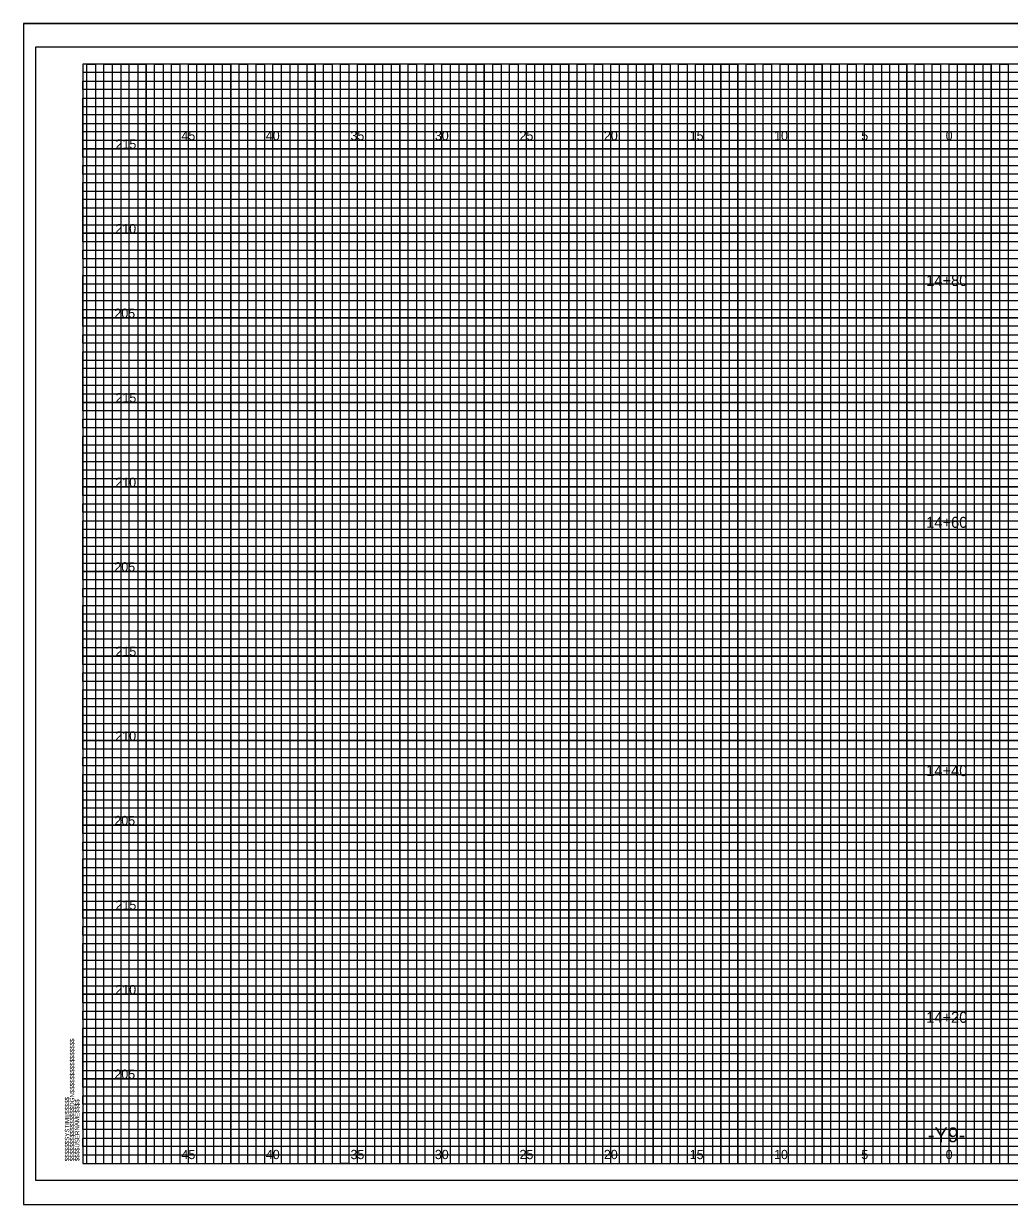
# Model space of a CAD drawing. Extents: x -4 to 103, y -2 to 492.
# Drawn here: x -3.5 to 54.8, y 280.9 to 350.7 of the extents above; entities that cross this region are included whole.
import ezdxf

# ---------------------------------------------------------------- set-up
doc = ezdxf.new("R2010")
doc.units = 0
for name, color, linetype in [('Old_Level_10', 7, 'Continuous'), ('Old_Level_16', 7, 'Continuous'), ('Old_Level_3', 7, 'Continuous'), ('Old_Level_5', 7, 'Continuous'), ('Old_Level_8', 7, 'Continuous'), ('Prop Dimension', 7, 'Continuous'), ('Prop Terminator CELL', 7, 'Continuous'), ('Prop XS Finish Grade', 7, 'Continuous'), ('Prop XS Finish Grade Earthwork', 7, 'Continuous'), ('Prop XS SE Text', 7, 'Continuous'), ('Prop XSC Text', 7, 'Continuous')]:
    doc.layers.add(name, color=color, linetype=linetype)

msp = doc.modelspace()

# ---------------------------------------------------------------- linework, layer by layer
at = {"layer": 'Old_Level_10'}
for p, q in [((1.25, 283.3), (1.25, 348.3)), ((3.75, 283.3), (3.75, 348.3)), ((6.25, 283.3), (6.25, 348.3)), ((8.75, 283.3), (8.75, 348.3)), ((11.25, 283.3), (11.25, 348.3)), ((13.75, 283.3), (13.75, 348.3)), ((16.25, 283.3), (16.25, 348.3)), ((18.75, 283.3), (18.75, 348.3)), ((21.25, 283.3), (21.25, 348.3)), ((23.75, 283.3), (23.75, 348.3)), ((26.25, 283.3), (26.25, 348.3)), ((28.75, 283.3), (28.75, 348.3)), ((31.25, 283.3), (31.25, 348.3)), ((33.75, 283.3), (33.75, 348.3)), ((36.25, 283.3), (36.25, 348.3)), ((38.75, 283.3), (38.75, 348.3)), ((41.25, 283.3), (41.25, 348.3)), ((43.75, 283.3), (43.75, 348.3)), ((46.25, 283.3), (46.25, 348.3)), ((48.75, 283.3), (48.75, 348.3)), ((51.25, 283.3), (51.25, 348.3)), ((53.75, 283.3), (53.75, 348.3)), ((0, 345.8), (74.25, 345.8)), ((0, 343.3), (102.5, 343.3)), ((0, 340.8), (102.5, 340.8)), ((0, 338.3), (102.5, 338.3)), ((0, 335.8), (102.5, 335.8)), ((0, 333.3), (102.5, 333.3)), ((0, 330.8), (102.5, 330.8)), ((0, 328.3), (102.5, 328.3)), ((0, 325.8), (102.5, 325.8)), ((0, 323.3), (102.5, 323.3)), ((0, 320.8), (102.5, 320.8)), ((0, 318.3), (102.5, 318.3)), ((0, 315.8), (102.5, 315.8)), ((0, 313.3), (102.5, 313.3)), ((0, 310.8), (102.5, 310.8)), ((0, 308.3), (102.5, 308.3)), ((0, 305.8), (102.5, 305.8)), ((0, 303.3), (102.5, 303.3)), ((0, 300.8), (102.5, 300.8)), ((0, 298.3), (102.5, 298.3)), ((0, 295.8), (102.5, 295.8)), ((0, 293.3), (102.5, 293.3)), ((0, 290.8), (102.5, 290.8)), ((0, 288.3), (102.5, 288.3)), ((0, 285.8), (102.5, 285.8))]:
    msp.add_line(p, q, dxfattribs=at)
at = {"layer": 'Old_Level_3'}
for p, q in [((-3.5, 350.7), (103.4, 350.7)), ((-3.5, 350.7), (-3.5, 280.875)), ((-3.5, 280.875), (103.4, 280.875))]:
    msp.add_line(p, q, dxfattribs=at)
at = {"layer": 'Old_Level_5'}
msp.add_lwpolyline([(103.4, 350.7), (-3.5, 350.7), (-3.5, 280.875), (103.4, 280.875)], close=True, dxfattribs=at)
at = {"layer": 'Old_Level_8'}
for points in [[(1.25, 283.3), (1.25, 348.3), (3.75, 348.3), (3.75, 283.3), (6.25, 283.3), (6.25, 348.3), (8.75, 348.3), (8.75, 283.3), (11.25, 283.3), (11.25, 348.3), (13.75, 348.3), (13.75, 283.3), (16.25, 283.3), (16.25, 348.3), (18.75, 348.3), (18.75, 283.3), (21.25, 283.3), (21.25, 348.3), (23.75, 348.3), (23.75, 283.3), (26.25, 283.3), (26.25, 348.3), (28.75, 348.3), (28.75, 283.3), (31.25, 283.3), (31.25, 348.3), (33.75, 348.3), (33.75, 283.3), (36.25, 283.3), (36.25, 348.3), (38.75, 348.3), (38.75, 283.3), (41.25, 283.3), (41.25, 348.3), (43.75, 348.3), (43.75, 283.3), (46.25, 283.3), (46.25, 348.3), (48.75, 348.3), (48.75, 283.3), (51.25, 283.3), (51.25, 348.3), (53.75, 348.3), (53.75, 283.3)], [(102.5, 343.3), (0, 343.3), (0, 345.8), (74.25, 345.8)], [(102.5, 338.3), (0, 338.3), (0, 340.8), (102.5, 340.8)], [(102.5, 333.3), (0, 333.3), (0, 335.8), (102.5, 335.8)], [(102.5, 328.3), (0, 328.3), (0, 330.8), (102.5, 330.8)], [(102.5, 323.3), (0, 323.3), (0, 325.8), (102.5, 325.8)], [(102.5, 318.3), (0, 318.3), (0, 320.8), (102.5, 320.8)], [(102.5, 313.3), (0, 313.3), (0, 315.8), (102.5, 315.8)], [(102.5, 308.3), (0, 308.3), (0, 310.8), (102.5, 310.8)], [(102.5, 303.3), (0, 303.3), (0, 305.8), (102.5, 305.8)], [(102.5, 298.3), (0, 298.3), (0, 300.8), (102.5, 300.8)], [(102.5, 293.3), (0, 293.3), (0, 295.8), (102.5, 295.8)], [(102.5, 288.3), (0, 288.3), (0, 290.8), (102.5, 290.8)], [(0, 285.8), (102.5, 285.8)]]:
    msp.add_lwpolyline(points, dxfattribs=at)
at = {"layer": 'Prop Dimension'}
for points in [[(0, 345.3), (0, 346.3), (74.25, 346.3), (74.25, 346.8), (0, 346.8), (0, 347.3), (74.25, 347.3), (74.25, 347.8), (0, 347.8)], [(0.25, 283.3), (0.25, 348.3), (0.75, 348.3), (0.75, 283.3), (1.75, 283.3), (1.75, 348.3), (2.25, 348.3), (2.25, 283.3), (2.75, 283.3), (2.75, 348.3), (3.25, 348.3), (3.25, 283.3), (4.25, 283.3), (4.25, 348.3), (4.75, 348.3), (4.75, 283.3), (5.25, 283.3), (5.25, 348.3), (5.75, 348.3), (5.75, 283.3), (6.75, 283.3), (6.75, 348.3), (7.25, 348.3), (7.25, 283.3), (7.75, 283.3), (7.75, 348.3), (8.25, 348.3), (8.25, 283.3), (9.25, 283.3), (9.25, 348.3), (9.75, 348.3), (9.75, 283.3), (10.25, 283.3), (10.25, 348.3), (10.75, 348.3), (10.75, 283.3), (11.75, 283.3), (11.75, 348.3), (12.25, 348.3), (12.25, 283.3), (12.75, 283.3), (12.75, 348.3), (13.25, 348.3), (13.25, 283.3), (14.25, 283.3), (14.25, 348.3), (14.75, 348.3), (14.75, 283.3), (15.75, 283.3), (15.25, 283.3), (15.25, 348.3), (15.75, 348.3), (15.75, 283.3), (16.75, 283.3), (16.75, 348.3), (17.25, 348.3), (17.25, 283.3), (17.75, 283.3), (17.75, 348.3), (18.25, 348.3), (18.25, 283.3), (19.25, 283.3), (19.25, 348.3), (19.75, 348.3), (19.75, 283.3), (20.25, 283.3), (20.25, 348.3), (20.75, 348.3), (20.75, 283.3), (21.75, 283.3), (21.75, 348.3), (22.25, 348.3), (22.25, 283.3), (22.75, 283.3), (22.75, 348.3), (23.25, 348.3), (23.25, 283.3), (24.25, 283.3), (24.25, 348.3), (24.75, 348.3), (24.75, 283.3), (25.25, 283.3), (25.25, 348.3), (25.75, 348.3), (25.75, 283.3), (26.75, 283.3), (26.75, 348.3), (27.25, 348.3), (27.25, 283.3), (27.75, 283.3), (27.75, 348.3), (28.25, 348.3), (28.25, 283.3), (29.25, 283.3), (29.25, 348.3), (29.75, 348.3), (29.75, 283.3), (30.25, 283.3), (30.25, 348.3), (30.75, 348.3), (30.75, 283.3)], [(30.75, 283.3), (31.75, 283.3), (31.75, 348.3), (32.25, 348.3), (32.25, 283.3), (32.75, 283.3), (32.75, 348.3), (33.25, 348.3), (33.25, 283.3), (34.25, 283.3), (34.25, 348.3), (34.75, 348.3), (34.75, 283.3), (35.25, 283.3), (35.25, 348.3), (35.75, 348.3), (35.75, 283.3), (36.75, 283.3), (36.75, 348.3), (37.25, 348.3), (37.25, 283.3), (37.75, 283.3), (37.75, 348.3), (37.75, 283.3)], [(38.25, 348.3), (38.25, 283.3), (39.25, 283.3), (39.25, 348.3), (39.75, 348.3), (39.75, 283.3), (40.25, 283.3), (40.25, 348.3), (40.75, 348.3), (40.75, 283.3), (41.75, 283.3), (41.75, 348.3), (42.25, 348.3), (42.25, 283.3), (42.75, 283.3), (42.75, 348.3), (43.25, 348.3), (43.25, 283.3), (43.75, 283.3), (44.25, 283.3), (44.25, 348.3), (44.75, 348.3), (44.75, 283.3), (45.25, 283.3), (45.25, 348.3), (45.75, 348.3), (45.75, 283.3), (46.75, 283.3), (46.75, 348.3), (47.25, 348.3), (47.25, 283.3), (47.75, 283.3), (47.75, 348.3), (48.25, 348.3), (48.25, 283.3), (49.25, 283.3), (49.25, 348.3), (49.75, 348.3), (49.75, 283.3), (50.25, 283.3), (50.25, 348.3), (50.75, 348.3), (50.75, 283.3), (51.75, 283.3), (51.75, 348.3), (52.25, 348.3), (52.25, 283.3), (52.75, 283.3), (52.75, 348.3), (53.25, 348.3), (53.25, 283.3), (54.25, 283.3), (54.25, 348.3), (54.75, 348.3), (54.75, 283.3), (55.25, 283.3)], [(102.5, 345.3), (0, 345.3)], [(102.5, 344.3), (0, 344.3), (0, 344.8), (102.5, 344.8)], [(102.5, 342.8), (0, 342.8), (0, 343.8), (102.5, 343.8)], [(102.5, 341.8), (0, 341.8), (0, 342.3), (102.5, 342.3)], [(102.5, 340.3), (0, 340.3), (0, 341.3), (102.5, 341.3)], [(102.5, 339.3), (0, 339.3), (0, 339.8), (102.5, 339.8)], [(102.5, 337.8), (0, 337.8), (0, 338.8), (102.5, 338.8)], [(102.5, 336.8), (0, 336.8), (0, 337.3), (102.5, 337.3)], [(0, 336.3), (102.5, 336.3)], [(102.5, 335.3), (0, 335.3)], [(102.5, 334.3), (0, 334.3), (0, 334.8), (102.5, 334.8)], [(102.5, 332.8), (0, 332.8), (0, 333.8), (102.5, 333.8)], [(102.5, 331.8), (0, 331.8), (0, 332.3), (102.5, 332.3)], [(102.5, 330.3), (0, 330.3), (0, 331.3), (102.5, 331.3)], [(102.5, 329.3), (0, 329.3), (0, 329.8), (102.5, 329.8)], [(102.5, 327.8), (0, 327.8), (0, 328.8), (102.5, 328.8)], [(102.5, 326.8), (0, 326.8), (0, 327.3), (102.5, 327.3)], [(102.5, 325.3), (0, 325.3), (0, 326.3), (102.5, 326.3)], [(102.5, 324.3), (0, 324.3), (0, 324.8), (102.5, 324.8)], [(102.5, 322.8), (0, 322.8), (0, 323.8), (102.5, 323.8)], [(102.5, 321.8), (0, 321.8), (0, 322.3), (102.5, 322.3)], [(102.5, 320.3), (0, 320.3), (0, 321.3), (102.5, 321.3)], [(102.5, 319.3), (0, 319.3), (0, 319.8), (102.5, 319.8)], [(102.5, 317.8), (0, 317.8), (0, 318.8), (102.5, 318.8)], [(102.5, 316.8), (0, 316.8), (0, 317.3), (102.5, 317.3)], [(102.5, 315.3), (0, 315.3), (0, 316.3), (102.5, 316.3)], [(102.5, 314.3), (0, 314.3), (0, 314.8)], [(0, 314.8), (102.5, 314.8)], [(102.5, 312.8), (0, 312.8), (0, 313.8), (102.5, 313.8)], [(102.5, 311.8), (0, 311.8), (0, 312.3), (102.5, 312.3)], [(102.5, 310.3), (0, 310.3), (0, 311.3), (102.5, 311.3)], [(102.5, 309.3), (0, 309.3), (0, 309.8), (102.5, 309.8)], [(102.5, 307.8), (0, 307.8), (0, 308.8), (102.5, 308.8)], [(102.5, 306.8), (0, 306.8), (0, 307.3), (102.5, 307.3)], [(102.5, 305.3), (0, 305.3), (0, 306.3), (102.5, 306.3)], [(102.5, 304.3), (0, 304.3), (0, 304.8), (102.5, 304.8)], [(102.5, 302.8), (0, 302.8), (0, 303.8), (102.5, 303.8)], [(102.5, 301.8), (0, 301.8), (0, 302.3), (102.5, 302.3)], [(102.5, 300.3), (0, 300.3), (0, 301.3), (102.5, 301.3)], [(102.5, 299.3), (0, 299.3), (0, 299.8), (102.5, 299.8)], [(102.5, 297.8), (0, 297.8), (0, 298.8), (102.5, 298.8)], [(102.5, 296.8), (0, 296.8), (0, 297.3), (102.5, 297.3)], [(102.5, 295.3), (0, 295.3), (0, 296.3), (102.5, 296.3)], [(102.5, 294.3), (0, 294.3), (0, 294.8), (102.5, 294.8)], [(102.5, 292.8), (0, 292.8), (0, 293.8), (102.5, 293.8)], [(102.5, 291.8), (0, 291.8), (0, 292.3), (102.5, 292.3)], [(102.5, 290.3), (0, 290.3), (0, 291.3), (102.5, 291.3)], [(102.5, 289.3), (0, 289.3), (0, 289.8), (102.5, 289.8)], [(102.5, 287.8), (0, 287.8), (0, 288.8), (102.5, 288.8)], [(102.5, 286.8), (0, 286.8), (0, 287.3), (102.5, 287.3)], [(102.5, 285.3), (0, 285.3), (0, 286.3), (102.5, 286.3)], [(102.5, 284.3), (0, 284.3), (0, 284.8), (102.5, 284.8)], [(0, 283.8), (102.5, 283.8)]]:
    msp.add_lwpolyline(points, dxfattribs=at)
at = {"layer": 'Prop XS SE Text'}
msp.add_lwpolyline([(103, 349.3), (-2.8, 349.3), (-2.8, 282.3), (103, 282.3)], close=True, dxfattribs=at)
at = {"layer": 'Prop XSC Text'}
msp.add_lwpolyline([(102.5, 348.3), (0, 348.3), (0, 283.3), (102.5, 283.3)], close=True, dxfattribs=at)

# ---------------------------------------------------------------- texts
at = {"layer": 'Old_Level_16'}
for s, p in [('45', (5.8399, 343.8)), ('40', (10.8313, 343.8)), ('35', (15.8399, 343.8)), ('30', (20.8313, 343.8)), ('25', (25.8399, 343.8)), ('20', (30.8313, 343.8)), ('15', (35.9058, 343.8)), ('10', (40.8971, 343.8)), ('5', (46.0574, 343.8)), ('0', (51.0488, 343.8)), ('0', (51.0488, 343.8)), ('45', (5.8399, 283.55)), ('40', (10.8313, 283.55)), ('35', (15.8399, 283.55)), ('30', (20.8313, 283.55)), ('25', (25.8399, 283.55)), ('20', (30.8313, 283.55)), ('15', (35.9058, 283.55)), ('10', (40.8971, 283.55)), ('5', (46.0574, 283.55)), ('0', (51.0488, 283.55)), ('0', (51.0488, 283.55))]:
    msp.add_text(s, height=0.55, dxfattribs=at).set_placement(p)
at = {"layer": 'Old_Level_8'}
msp.add_text('040397', height=0.0025, rotation=90, dxfattribs=at).set_placement((-0.0007, 348.2864))
at = {"layer": 'Prop Terminator CELL'}
msp.add_text('-Y9-', height=0.875, dxfattribs=at).set_placement((49.9985, 284.55))
at = {"layer": 'Prop XS Finish Grade'}
for s, p in [('14+80', (49.8934, 335.1834)), ('14+60', (49.8934, 320.8839)), ('14+40', (49.8934, 306.2037)), ('14+20', (49.8934, 291.613))]:
    msp.add_text(s, height=0.65, dxfattribs=at).set_placement(p)
at = {"layer": 'Prop XS Finish Grade Earthwork'}
for s, p in [('215', (1.9383, 343.3)), ('210', (1.9296, 338.3)), ('205', (1.8724, 333.3)), ('215', (1.9383, 328.3)), ('210', (1.9296, 323.3)), ('205', (1.8724, 318.3)), ('215', (1.9383, 313.3)), ('210', (1.9296, 308.3)), ('205', (1.8724, 303.3)), ('215', (1.9383, 298.3)), ('210', (1.9296, 293.3)), ('205', (1.8724, 288.3))]:
    msp.add_text(s, height=0.55, dxfattribs=at).set_placement(p)
at = {"layer": 'Prop XSC Text'}
for s, p in [('$$$$$$$$$$$$$$$$DGN$$$$$$$$$$$$$$$$', (-0.5, 283.425)), ('$$$$$$SYSTIME$$$$$', (-0.7973, 283.4247)), ('$$$$USERNAME$$$$', (-0.2, 283.425))]:
    msp.add_text(s, height=0.2625, rotation=90, dxfattribs=at).set_placement(p)

doc.saveas('drawing.dxf')
